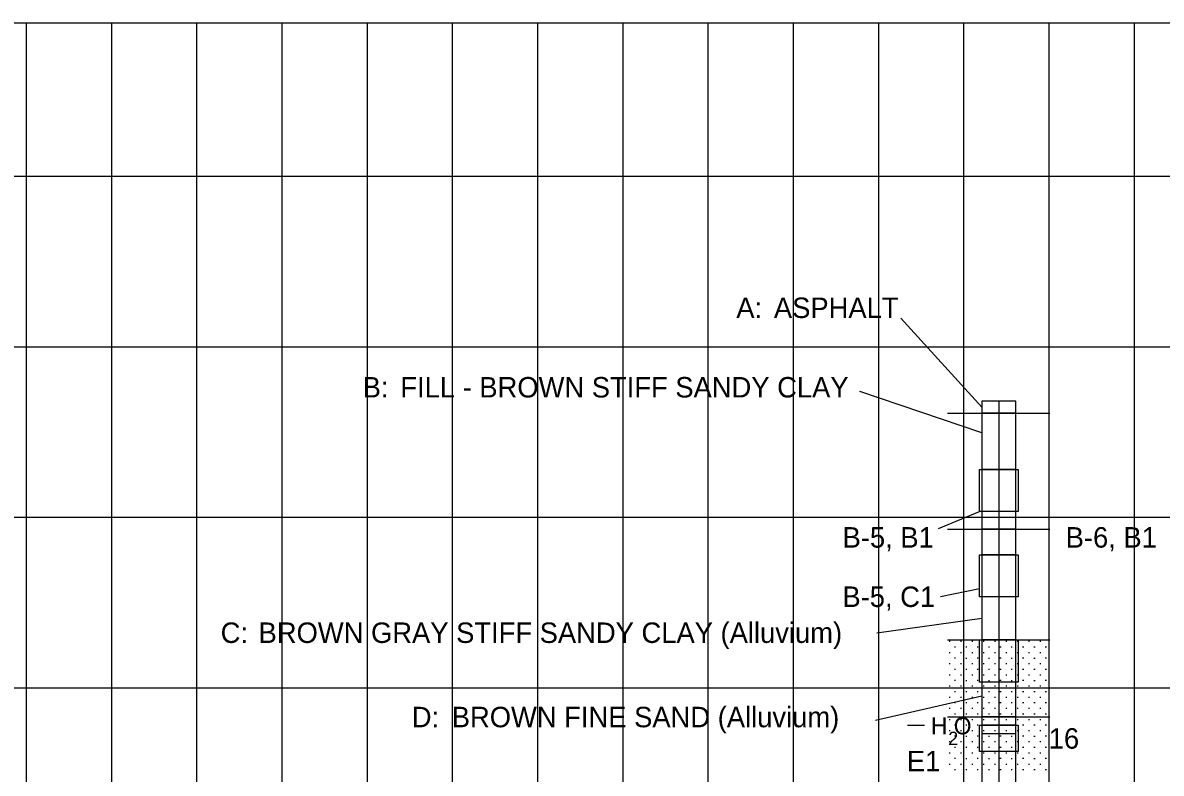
# Model space of a CAD drawing. Extents: x -290 to 297, y 616 to 861.
# Drawn here: x -130.4 to 3.2, y 700 to 788 of the extents above; entities that cross this region are included whole.
import ezdxf

# ---------------------------------------------------------------- set-up
doc = ezdxf.new("R2010")
doc.units = 0
for name, color, linetype in [('Boundary', 7, 'Continuous'), ('Cell', 7, 'Continuous'), ('Default', 7, 'Continuous'), ('DisROW Proposed Temp Easements', 7, 'Continuous'), ('Draft_4', 7, 'Continuous'), ('MeshTop', 7, 'Continuous'), ('Point', 7, 'Continuous'), ('SewerSanitary', 7, 'Continuous'), ('SewerStormPipe', 7, 'Continuous'), ('SheetText', 7, 'Continuous'), ('TextAlignment', 7, 'Continuous'), ('TextAlignmentSml', 7, 'Continuous'), ('Utility-Water - alignment', 7, 'Continuous'), ('V-SWLK-CONC', 7, 'Continuous')]:
    doc.layers.add(name, color=color, linetype=linetype)

msp = doc.modelspace()

# ---------------------------------------------------------------- linework, layer by layer
at = {"layer": 'Boundary'}
msp.add_line((-13.91, 705.6), (-17.91, 705.6), dxfattribs=at)
at = {"layer": 'Cell'}
msp.add_line((-13.91, 704.6), (-17.91, 704.6), dxfattribs=at)
at = {"layer": 'Default'}
for p, q in [((-15.91, 743.6), (-15.91, 682.6)), ((-13.91, 742.2), (-17.91, 742.2)), ((-13.91, 728.6), (-17.91, 728.6)), ((-13.91, 715.6), (-17.91, 715.6)), ((-13.91, 706.6), (-17.91, 706.6))]:
    msp.add_line(p, q, dxfattribs=at)
at = {"layer": 'DisROW Proposed Temp Easements'}
for p, q in [((-24.64, 705.58), (-26.64, 705.58)), ((-17.91, 705.6), (-15.91, 705.6))]:
    msp.add_line(p, q, dxfattribs=at)
for points in [[(-18.16, 735.6), (-13.65, 735.6), (-13.65, 730.66), (-18.16, 730.66)], [(-18.16, 725.6), (-13.65, 725.6), (-13.65, 720.66), (-18.16, 720.66)], [(-18.16, 715.6), (-13.65, 715.6), (-13.65, 710.66), (-18.16, 710.66)], [(-18.19, 705.6), (-13.62, 705.6), (-13.62, 702.5), (-18.19, 702.5)]]:
    msp.add_lwpolyline(points, close=True, dxfattribs=at)
at = {"layer": 'Draft_4'}
for points in [[(-13.91, 715.6), (-17.91, 715.6), (-17.91, 706.6), (-13.91, 706.6)], [(-13.91, 706.6), (-17.91, 706.6), (-17.91, 682.6), (-13.91, 682.6)]]:
    msp.add_lwpolyline(points, close=True, dxfattribs=at)
at = {"layer": 'MeshTop'}
msp.add_lwpolyline([(-13.91, 743.6), (-17.91, 743.6), (-17.91, 742.2), (-13.91, 742.2)], close=True, dxfattribs=at)
at = {"layer": 'Point'}
msp.add_lwpolyline([(-13.91, 728.6), (-17.91, 728.6), (-17.91, 715.6), (-13.91, 715.6)], close=True, dxfattribs=at)
at = {"layer": 'SewerSanitary'}
for p, q in [((-13.91, 735.6), (-17.91, 735.6)), ((-13.91, 725.6), (-17.91, 725.6)), ((-13.91, 715.6), (-17.91, 715.6))]:
    msp.add_line(p, q, dxfattribs=at)
at = {"layer": 'SewerStormPipe'}
msp.add_line((-13.91, 705.6), (-17.91, 705.6), dxfattribs=at)
at = {"layer": 'SheetText'}
msp.add_line((-275.61, 787.99), (284.21, 787.99), dxfattribs=at)
at = {"layer": 'TextAlignment'}
for p, q in [((-120, 630), (-120, 787.99)), ((-100, 630), (-100, 787.99)), ((-80, 630), (-80, 787.99)), ((-60, 630), (-60, 787.99)), ((-40, 630), (-40, 787.99)), ((-20, 630), (-20, 787.99)), ((0, 630), (0, 787.99)), ((-275.61, 770), (284.21, 770)), ((-275.61, 730), (284.21, 730))]:
    msp.add_line(p, q, dxfattribs=at)
at = {"layer": 'TextAlignmentSml'}
for p, q in [((-130, 630), (-130, 787.99)), ((-110, 630), (-110, 787.99)), ((-90, 630), (-90, 787.99)), ((-70, 630), (-70, 787.99)), ((-50, 630), (-50, 787.99)), ((-30, 630), (-30, 787.99)), ((-10, 630), (-10, 787.99)), ((-275.61, 750), (284.21, 750)), ((-275.61, 710), (284.21, 710))]:
    msp.add_line(p, q, dxfattribs=at)
at = {"layer": 'Utility-Water - alignment'}
msp.add_lwpolyline([(-13.91, 742.2), (-17.91, 742.2), (-17.91, 728.6), (-13.91, 728.6)], close=True, dxfattribs=at)
at = {"layer": 'V-SWLK-CONC'}
for p, q in [((-17.91, 742.9), (-27.39, 753.36)), ((-17.91, 739.91), (-32.22, 744.74)), ((-21.91, 742.2), (-9.91, 742.2)), ((-22.97, 728.67), (-18.16, 730.66)), ((-21.91, 728.6), (-9.91, 728.6)), ((-22.75, 720.68), (-18.16, 721.64)), ((-30.23, 716.45), (-17.91, 718.17)), ((-21.91, 715.6), (-9.91, 715.6)), ((-21.74, 715.44), (-21.61, 715.44)), ((-21.11, 714.8), (-20.98, 714.8)), ((-20.42, 715.44), (-20.29, 715.44)), ((-19.78, 714.78), (-19.65, 714.78)), ((-19.08, 715.44), (-18.95, 715.44)), ((-18.45, 714.8), (-18.32, 714.8)), ((-17.76, 715.44), (-17.63, 715.44)), ((-17.12, 714.78), (-16.99, 714.78)), ((-16.42, 715.44), (-16.29, 715.44)), ((-15.79, 714.8), (-15.65, 714.8)), ((-15.1, 715.44), (-14.97, 715.44)), ((-14.46, 714.78), (-14.33, 714.78)), ((-13.76, 715.44), (-13.63, 715.44)), ((-13.13, 714.8), (-12.99, 714.8)), ((-12.44, 715.44), (-12.31, 715.44)), ((-11.8, 714.78), (-11.66, 714.78)), ((-11.1, 715.44), (-10.97, 715.44)), ((-10.47, 714.8), (-10.33, 714.8)), ((-21.74, 714.13), (-21.61, 714.13)), ((-21.11, 713.49), (-20.98, 713.49)), ((-20.42, 714.13), (-20.29, 714.13)), ((-19.78, 713.48), (-19.65, 713.48)), ((-19.08, 714.13), (-18.95, 714.13)), ((-18.45, 713.49), (-18.32, 713.49)), ((-17.76, 714.13), (-17.63, 714.13)), ((-17.12, 713.48), (-16.99, 713.48)), ((-16.42, 714.13), (-16.29, 714.13)), ((-15.79, 713.49), (-15.65, 713.49)), ((-15.1, 714.13), (-14.97, 714.13)), ((-14.46, 713.48), (-14.33, 713.48)), ((-13.76, 714.13), (-13.63, 714.13)), ((-13.13, 713.49), (-12.99, 713.49)), ((-12.44, 714.13), (-12.31, 714.13)), ((-11.8, 713.48), (-11.66, 713.48)), ((-11.1, 714.13), (-10.97, 714.13)), ((-10.47, 713.49), (-10.33, 713.49)), ((-21.74, 712.82), (-21.61, 712.82)), ((-21.11, 712.18), (-20.98, 712.18)), ((-20.42, 712.82), (-20.29, 712.82)), ((-19.78, 712.17), (-19.65, 712.17)), ((-19.08, 712.82), (-18.95, 712.82)), ((-18.45, 712.18), (-18.32, 712.18)), ((-17.76, 712.82), (-17.63, 712.82)), ((-17.12, 712.17), (-16.99, 712.17)), ((-16.42, 712.82), (-16.29, 712.82)), ((-15.79, 712.18), (-15.65, 712.18)), ((-15.1, 712.82), (-14.97, 712.82)), ((-14.46, 712.17), (-14.33, 712.17)), ((-13.76, 712.82), (-13.63, 712.82)), ((-13.13, 712.18), (-12.99, 712.18)), ((-12.44, 712.82), (-12.31, 712.82)), ((-11.8, 712.17), (-11.66, 712.17)), ((-11.1, 712.82), (-10.97, 712.82)), ((-10.47, 712.18), (-10.33, 712.18)), ((-21.74, 711.51), (-21.61, 711.51)), ((-21.11, 710.87), (-20.98, 710.87)), ((-20.42, 711.51), (-20.29, 711.51)), ((-19.78, 710.86), (-19.65, 710.86)), ((-19.08, 711.51), (-18.95, 711.51)), ((-18.45, 710.87), (-18.32, 710.87)), ((-17.76, 711.51), (-17.63, 711.51)), ((-17.12, 710.86), (-16.99, 710.86)), ((-16.42, 711.51), (-16.29, 711.51)), ((-15.79, 710.87), (-15.65, 710.87)), ((-15.1, 711.51), (-14.97, 711.51)), ((-14.46, 710.86), (-14.33, 710.86)), ((-13.76, 711.51), (-13.63, 711.51)), ((-13.13, 710.87), (-12.99, 710.87)), ((-12.44, 711.51), (-12.31, 711.51)), ((-11.8, 710.86), (-11.66, 710.86)), ((-11.1, 711.51), (-10.97, 711.51)), ((-10.47, 710.87), (-10.33, 710.87)), ((-21.74, 710.21), (-21.61, 710.21)), ((-21.11, 709.57), (-20.98, 709.57)), ((-20.42, 710.21), (-20.29, 710.21)), ((-19.78, 709.55), (-19.65, 709.55)), ((-19.08, 710.21), (-18.95, 710.21)), ((-18.45, 709.57), (-18.32, 709.57)), ((-17.76, 710.21), (-17.63, 710.21)), ((-17.12, 709.55), (-16.99, 709.55)), ((-16.42, 710.21), (-16.29, 710.21)), ((-15.79, 709.57), (-15.65, 709.57)), ((-15.1, 710.21), (-14.97, 710.21)), ((-14.46, 709.55), (-14.33, 709.55)), ((-13.76, 710.21), (-13.63, 710.21)), ((-13.13, 709.57), (-12.99, 709.57)), ((-12.44, 710.21), (-12.31, 710.21)), ((-11.8, 709.55), (-11.66, 709.55)), ((-11.1, 710.21), (-10.97, 710.21)), ((-10.47, 709.57), (-10.33, 709.57)), ((-30.39, 706.21), (-17.91, 709.05)), ((-21.74, 708.9), (-21.61, 708.9)), ((-21.11, 708.26), (-20.98, 708.26)), ((-20.42, 708.9), (-20.29, 708.9)), ((-19.78, 708.25), (-19.65, 708.25)), ((-19.08, 708.9), (-18.95, 708.9)), ((-18.45, 708.26), (-18.32, 708.26)), ((-17.76, 708.9), (-17.63, 708.9)), ((-17.12, 708.25), (-16.99, 708.25)), ((-16.42, 708.9), (-16.29, 708.9)), ((-15.79, 708.26), (-15.65, 708.26)), ((-15.1, 708.9), (-14.97, 708.9)), ((-14.46, 708.25), (-14.33, 708.25)), ((-13.76, 708.9), (-13.63, 708.9)), ((-13.13, 708.26), (-12.99, 708.26)), ((-12.44, 708.9), (-12.31, 708.9)), ((-11.8, 708.25), (-11.66, 708.25)), ((-11.1, 708.9), (-10.97, 708.9)), ((-10.47, 708.26), (-10.33, 708.26)), ((-21.74, 707.59), (-21.61, 707.59)), ((-21.11, 706.95), (-20.98, 706.95)), ((-20.42, 707.59), (-20.29, 707.59)), ((-19.78, 706.94), (-19.65, 706.94)), ((-19.08, 707.59), (-18.95, 707.59)), ((-18.45, 706.95), (-18.32, 706.95)), ((-17.76, 707.59), (-17.63, 707.59)), ((-17.12, 706.94), (-16.99, 706.94)), ((-16.42, 707.59), (-16.29, 707.59)), ((-15.79, 706.95), (-15.65, 706.95)), ((-15.1, 707.59), (-14.97, 707.59)), ((-14.46, 706.94), (-14.33, 706.94)), ((-13.76, 707.59), (-13.63, 707.59)), ((-13.13, 706.95), (-12.99, 706.95)), ((-12.44, 707.59), (-12.31, 707.59)), ((-11.8, 706.94), (-11.66, 706.94)), ((-11.1, 707.59), (-10.97, 707.59)), ((-10.47, 706.95), (-10.33, 706.95)), ((-21.91, 706.6), (-9.91, 706.6)), ((-21.74, 706.28), (-21.61, 706.28)), ((-21.11, 705.64), (-20.98, 705.64)), ((-20.42, 706.28), (-20.29, 706.28)), ((-19.78, 705.63), (-19.65, 705.63)), ((-19.08, 706.28), (-18.95, 706.28)), ((-18.45, 705.64), (-18.32, 705.64)), ((-17.76, 706.28), (-17.63, 706.28)), ((-17.12, 705.63), (-16.99, 705.63)), ((-16.42, 706.28), (-16.29, 706.28)), ((-15.79, 705.64), (-15.65, 705.64)), ((-15.1, 706.28), (-14.97, 706.28)), ((-14.46, 705.63), (-14.33, 705.63)), ((-13.76, 706.28), (-13.63, 706.28)), ((-13.13, 705.64), (-12.99, 705.64)), ((-12.44, 706.28), (-12.31, 706.28)), ((-11.8, 705.63), (-11.66, 705.63)), ((-11.1, 706.28), (-10.97, 706.28)), ((-10.47, 705.64), (-10.33, 705.64)), ((-21.74, 704.98), (-21.61, 704.98)), ((-21.11, 704.34), (-20.98, 704.34)), ((-20.42, 704.98), (-20.29, 704.98)), ((-19.78, 704.32), (-19.65, 704.32)), ((-19.08, 704.98), (-18.95, 704.98)), ((-18.45, 704.34), (-18.32, 704.34)), ((-17.76, 704.98), (-17.63, 704.98)), ((-17.12, 704.32), (-16.99, 704.32)), ((-16.42, 704.98), (-16.29, 704.98)), ((-15.79, 704.34), (-15.65, 704.34)), ((-15.1, 704.98), (-14.97, 704.98)), ((-14.46, 704.32), (-14.33, 704.32)), ((-13.76, 704.98), (-13.63, 704.98)), ((-13.13, 704.34), (-12.99, 704.34)), ((-12.44, 704.98), (-12.31, 704.98)), ((-11.8, 704.32), (-11.66, 704.32)), ((-11.1, 704.98), (-10.97, 704.98)), ((-10.47, 704.34), (-10.33, 704.34)), ((-21.74, 703.67), (-21.61, 703.67)), ((-21.11, 703.03), (-20.98, 703.03)), ((-20.42, 703.67), (-20.29, 703.67)), ((-19.78, 703.02), (-19.65, 703.02)), ((-19.08, 703.67), (-18.95, 703.67)), ((-18.45, 703.03), (-18.32, 703.03)), ((-17.76, 703.67), (-17.63, 703.67)), ((-17.12, 703.02), (-16.99, 703.02)), ((-16.42, 703.67), (-16.29, 703.67)), ((-15.79, 703.03), (-15.65, 703.03)), ((-15.1, 703.67), (-14.97, 703.67)), ((-14.46, 703.02), (-14.33, 703.02)), ((-13.76, 703.67), (-13.63, 703.67)), ((-13.13, 703.03), (-12.99, 703.03)), ((-12.44, 703.67), (-12.31, 703.67)), ((-11.8, 703.02), (-11.66, 703.02)), ((-11.1, 703.67), (-10.97, 703.67)), ((-10.47, 703.03), (-10.33, 703.03)), ((-21.74, 702.36), (-21.61, 702.36)), ((-21.11, 701.72), (-20.98, 701.72)), ((-20.42, 702.36), (-20.29, 702.36)), ((-19.78, 701.71), (-19.65, 701.71)), ((-19.08, 702.36), (-18.95, 702.36)), ((-18.45, 701.72), (-18.32, 701.72)), ((-17.76, 702.36), (-17.63, 702.36)), ((-17.12, 701.71), (-16.99, 701.71)), ((-16.42, 702.36), (-16.29, 702.36)), ((-15.79, 701.72), (-15.65, 701.72)), ((-15.1, 702.36), (-14.97, 702.36)), ((-14.46, 701.71), (-14.33, 701.71)), ((-13.76, 702.36), (-13.63, 702.36)), ((-13.13, 701.72), (-12.99, 701.72)), ((-12.44, 702.36), (-12.31, 702.36)), ((-11.8, 701.71), (-11.66, 701.71)), ((-11.1, 702.36), (-10.97, 702.36)), ((-10.47, 701.72), (-10.33, 701.72)), ((-21.74, 701.05), (-21.61, 701.05)), ((-21.11, 700.41), (-20.98, 700.41)), ((-20.42, 701.05), (-20.29, 701.05)), ((-19.78, 700.4), (-19.65, 700.4)), ((-19.08, 701.05), (-18.95, 701.05)), ((-18.45, 700.41), (-18.32, 700.41)), ((-17.76, 701.05), (-17.63, 701.05)), ((-17.12, 700.4), (-16.99, 700.4)), ((-16.42, 701.05), (-16.29, 701.05)), ((-15.79, 700.41), (-15.65, 700.41)), ((-15.1, 701.05), (-14.97, 701.05)), ((-14.46, 700.4), (-14.33, 700.4)), ((-13.76, 701.05), (-13.63, 701.05)), ((-13.13, 700.41), (-12.99, 700.41)), ((-12.44, 701.05), (-12.31, 701.05)), ((-11.8, 700.4), (-11.66, 700.4)), ((-11.1, 701.05), (-10.97, 701.05)), ((-10.47, 700.41), (-10.33, 700.41))]:
    msp.add_line(p, q, dxfattribs=at)

# ---------------------------------------------------------------- texts
at = {"layer": 'DisROW Proposed Temp Easements'}
for s, height, p in [('H O', 2, (-23.87, 704.53)), ('2', 1.57, (-21.84, 703.27))]:
    msp.add_text(s, height=height, dxfattribs=at).set_placement(p)
at = {"layer": 'V-SWLK-CONC'}
for s, p in [('A: ', (-46.71, 753.36)), ('ASPHALT', (-42.3, 753.36)), ('B: ', (-90.56, 744.04)), ('FILL - BROWN STIFF SANDY CLAY', (-86.14, 744.04)), ('B-5, B1', (-34.24, 726.43)), ('B-6, B1', (-8.06, 726.43)), ('B-5, C1', (-34.26, 719.47)), ('C: ', (-107.22, 715.25)), ('BROWN GRAY STIFF SANDY CLAY (Alluvium)', (-102.77, 715.25)), ('D: ', (-84.79, 705.36)), ('BROWN FINE SAND (Alluvium)', (-80.1, 705.36)), ('16', (-10.05, 702.85)), ('E1', (-26.7, 700.19))]:
    msp.add_text(s, height=2.4, dxfattribs=at).set_placement(p)

doc.saveas('drawing.dxf')
